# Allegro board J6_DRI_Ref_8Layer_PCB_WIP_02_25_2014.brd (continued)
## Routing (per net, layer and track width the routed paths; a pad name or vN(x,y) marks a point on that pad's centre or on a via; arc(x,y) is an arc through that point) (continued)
H_DDR1_A13: length 131.1
  TOP w0.102: v1(57.54,55.59) U52.AF18
  TOP w0.127: U65.T3 TP1MA23.1 ; TP1MC23.1 55.45,20.25 U67.N3 ; RN6.3 v1(62.39,19.64) ; U66.T3 TP1MB23.1
  L3-SIGNAL w0.114: TP1MB23.1 43.53,20.09 42.32,20.09 41.76,19.54 41.05,19.54 40.54,20.04 40.08,20.04 39.62,20.5 38.84,20.5 38.25,19.92 37.69,19.92 36.83,19.05 34.77,19.05 34.24,19.59 33.93,19.59 33.45,19.1 33.12,19.1 32.84,19.38 32.84,19.61 32.61,19.84 TP1MA23.1 ; v1(62.39,19.64) 61.99,19.25 56.78,19.25 56.17,19.85 TP1MC23.1
  BOTTOM w0.127: TP1MB23.1 45.44,19.84 45.8,20.2 46.94,20.2 47.93,19.2 48.95,19.2 49.38,19.64 49.78,19.64 49.89,19.54 49.89,19.15 49.99,19.05 50.19,19.05 50.29,19.15 50.29,19.54 50.42,19.66 51.13,19.66 51.28,19.51 51.28,19.2 51.38,19.1 51.74,19.1 51.92,19.28 52.33,19.28 52.51,19.1 52.92,19.1 53.1,19.28 53.51,19.28 53.69,19.1 54.1,19.1 54.28,19.28 54.58,19.28 54.77,19.1 55.09,19.1 TP1MC23.1 ; TP1MA23.1 30.85,20.07 29.34,20.07 28.96,19.69 28.47,19.69 28.3,19.87 27.99,19.87 27.81,19.69 25.68,19.69 25.35,20.02 25.35,20.47 25.21,20.61 24.75,20.61 24.24,21.13 24.24,21.4 24.48,21.63 24.48,21.8 24.36,21.92 24.19,21.92 23.95,21.68 23.56,21.68 23.06,22.18 23.06,22.43 23.19,22.56 23.6,22.56 23.88,22.84 23.88,23.6 23.42,24.06 23.42,24.2 23.61,24.4 23.61,24.55 23.47,24.69 23.33,24.69 23.09,24.45 22.92,24.45 22.8,24.57 22.8,24.74 23.04,24.98 23.04,25.12 22.9,25.27 22.75,25.27 22.53,25.04 22.36,25.04 21.56,25.83 20.68,25.83 20.42,26.09 20.42,26.22 20.52,26.32 20.8,26.32 20.9,26.42 20.9,26.6 20.8,26.7 20.6,26.7 20.5,26.8 20.5,26.98 20.6,27.08 21.31,27.08 21.41,27.18 21.41,27.38 21.31,27.49 20.62,27.49 20.52,27.59 20.52,27.79 20.62,27.89 21.31,27.89 21.41,27.99 21.41,28.2 21.31,28.3 20.62,28.3 20.52,28.4 20.52,28.6 20.62,28.7 21.31,28.7 21.41,28.81 21.41,29.01 21.31,29.11 20.62,29.11 20.52,29.21 20.52,29.42 20.62,29.52 21.31,29.52 21.41,29.62 21.41,29.82 21.31,29.92 20.62,29.92 20.52,30.03 20.52,30.23 20.62,30.33 21.31,30.33 21.41,30.43 21.41,30.63 21.31,30.74 20.62,30.74 20.52,30.84 20.52,31.45 20.35,31.63 20.14,31.63 20.02,31.75 20.02,32.41 20.12,32.51 20.79,32.51 20.9,32.63 20.9,32.8 20.79,32.92 20.12,32.92 20.02,33.02 20.02,33.23 20.12,33.33 20.96,33.33 21.08,33.45 21.08,33.61 20.96,33.73 20.12,33.73 20.02,33.84 20.02,34.04 20.12,34.14 20.79,34.14 20.9,34.26 20.9,34.43 20.79,34.55 20.32,34.55 20.19,34.67 20.19,34.85 20.32,34.98 21.29,34.98 23.06,36.76 23.06,36.96 35.46,49.35 40.46,49.35 40.72,49.1 40.94,49.1 41.05,49.2 41.05,49.36 41.17,49.48 41.33,49.48 41.45,49.36 41.45,49.2 41.55,49.1 41.76,49.1 41.86,49.2 41.86,49.36 41.98,49.48 42.15,49.48 42.27,49.36 42.27,49.2 42.37,49.1 42.57,49.1 42.67,49.2 42.67,49.36 42.79,49.48 42.96,49.48 43.08,49.36 43.08,49.2 43.18,49.1 43.38,49.1 43.48,49.2 43.48,49.36 43.6,49.48 43.77,49.48 43.89,49.36 43.89,49.2 43.99,49.1 44.86,49.1 49.68,53.93 50.29,53.93 51.65,55.29 57.23,55.29 v1(57.54,55.59)
H_DDR1_A14: length 116.3
  TOP w0.102: v1(59.13,56.41) U52.AE17
  TOP w0.127: TP1MC24.1 58.65,20.25 U67.N7 ; U65.T7 TP1MA24.1 ; U66.T7 TP1MB24.1
  L3-SIGNAL w0.114: v2(19.38,25.22) 19.38,32.59 21,34.21 21,34.35 20.89,34.46 20.89,34.6 21.03,34.75 21.17,34.75 21.28,34.64 21.43,34.64 21.57,34.78 21.57,35.15 21.74,35.32 22.18,35.32 29.98,43.13 31.83,43.13 34.75,46.05 40.84,46.05 47.32,52.53 51.89,52.53 52.35,52.99 54.94,52.99 56.57,54.61 58.39,54.61 58.9,55.12 59.36,55.12 59.54,55.3 59.54,56 v1(59.13,56.41)
  BOTTOM w0.127: v2(19.38,25.22) 22.89,21.72 22.89,21.03 25.02,18.9 29.34,18.9 29.57,19.13 30.15,19.13 30.28,19 30.78,19 31.17,19.38 33.05,19.38 TP1MA24.1 34.25,19.76 34.72,19.29 34.72,19.05 34.9,18.87 35.84,18.87 36.02,18.7 36.4,18.7 36.58,18.87 37.34,18.87 37.59,18.62 38.71,18.62 39.07,18.98 39.83,18.98 40.01,18.8 42.06,18.8 42.39,19.13 42.77,19.13 42.93,18.98 43.38,18.98 43.73,19.32 44.89,19.32 45.34,18.87 45.69,18.87 46.13,19.31 TP1MB24.1 46.74,19.76 47.88,18.62 49,18.62 49.28,18.9 49.56,18.9 49.83,18.62 51.32,18.62 51.33,18.61 56.1,18.61 56.29,18.8 56.64,18.8 56.88,18.56 57.06,18.56 57.21,18.71 57.21,18.89 56.88,19.22 56.88,19.36 57.02,19.51 57.16,19.51 57.46,19.21 57.61,19.21 TP1MC24.1 58.82,20.42 59.28,20.42 60.5,19.2 62.55,19.2 62.98,19.64 RN17.2
H_DDR1_A15: length 103.1
  TOP w0.102: U52.AD18 v1(59.98,55.63)
  TOP w0.127: TP1MC9.1 U67.J7 ; U65.M7 33.66,23.69 33.53,23.82 33.53,23.97 33.66,24.09 TP1MA11.1 ; TP1MB11.1 46.36,24.09 46.23,23.97 46.23,23.82 46.36,23.69 U66.M7
  L3-SIGNAL w0.114: TP1MA11.1 35.32,24.09 35.74,24.51 36.91,24.51 36.93,24.49 45.05,24.49 45.71,23.82 46.09,23.82 46.37,24.09 TP1MB11.1
  BOTTOM w0.102: 60.33,52.89 60.33,54.95 59.98,55.31 ; 59.46,52.02 58.98,52.02 58.94,52.05 58.16,52.05
  BOTTOM w0.127: 58.16,52.05 57.81,52.4 57.2,52.4 56.01,51.21 54.09,51.21 53.71,50.83 50.37,50.83 40.49,40.95 34.21,40.95 33.6,40.34 32.59,40.34 28.46,36.21 27.97,36.21 27,35.24 27,30.3 26.37,29.67 26.37,28.86 25.81,28.3 25.81,26.34 26.16,25.99 27.38,25.99 27.48,26.09 29.65,26.09 29.89,25.85 29.89,25.53 30.12,25.3 30.92,25.3 31.06,25.16 32.02,25.16 32.33,25.48 32.59,25.48 32.72,25.35 32.72,25.1 32.33,24.72 32.33,24.41 32.94,23.8 33.53,23.8 33.82,24.09 TP1MA11.1 ; 59.98,55.31 v1(59.98,55.63) ; 59.46,52.02 60.33,52.89 ; RN13.1 63.6,25.93 62.36,24.69 61.59,24.69 61.21,25.07 60.4,25.07 60.38,25.05 58.88,25.05 58.57,24.74 58.34,24.74 TP1MC9.1 58.01,24.41 57.35,24.41 57.23,24.54 56.64,24.54 56.31,24.21 55.88,24.21 55.52,24.56 55.52,24.87 55.89,25.24 55.89,25.39 55.79,25.49 55.64,25.49 55.11,24.95 55.11,24.77 54.92,24.59 54.76,24.59 54.64,24.72 54.64,24.92 54.51,25.05 54.08,25.05 53.52,24.49 51.16,24.49 51,24.34 50.22,24.34 50.06,24.49 48.41,24.49 48.18,24.26 48.18,24.01 47.98,23.8 47.28,23.8 TP1MB11.1
H_DDR1_BA0: length 128.3
  TOP w0.102: v1(57.53,56.44) U52.AF17
  TOP w0.127: U65.M2 29.88,23.43 29.78,23.33 29.63,23.33 29.48,23.48 TP1MA9.1 ; TP1MC10.1 U67.J2 ; RN2.4 v1(63.02,25.93) ; U66.M2 42.58,23.43 42.48,23.33 42.33,23.33 42.18,23.48 TP1MB9.1
  L3-SIGNAL w0.114: v1(63.02,25.93) 62.4,25.93 60.74,24.27 59.69,24.27 59.41,23.99 55.51,23.99 55.26,24.24 54.63,24.24 TP1MC10.1 53.86,24.24 52.08,24.24 51.36,23.52 50.45,23.52 49.83,22.91 46.77,22.91 46.58,23.09 45.39,23.09 44.96,23.52 42.75,23.52 TP1MB9.1 41.76,23.68 38.38,23.68 37.97,24.08 36.53,24.08 36.41,23.97 36.41,23.71 36.27,23.57 35.79,23.57 35.56,23.8 34.86,23.8 34.75,23.69 33.97,23.69 33.86,23.8 33.53,23.8 33.43,23.69 30.55,23.69 30.38,23.52 30.05,23.52 TP1MA9.1 29.09,23.7 26.57,23.7 26.21,24.06 23.52,24.06 22.94,24.64 22.94,26.88 22.81,27 22.5,27 22.38,26.88 v2(22.38,23.7)
  BOTTOM w0.127: v1(57.53,56.44) 57.12,56.44 56.48,55.8 51.2,55.8 50.04,54.64 49.45,54.64 45.06,50.24 35.26,50.24 32.13,47.12 31.99,47.12 31.76,47.35 31.6,47.35 31.48,47.23 31.48,47.06 31.7,46.83 31.7,46.69 31.56,46.55 31.41,46.55 31.19,46.77 31.02,46.77 30.9,46.65 30.9,46.48 31.13,46.26 31.13,46.12 30.98,45.97 30.84,45.97 30.61,46.2 30.45,46.2 30.33,46.08 30.33,45.91 30.55,45.68 30.55,45.54 30.41,45.4 30.26,45.4 30.04,45.62 29.87,45.62 29.75,45.5 29.75,45.33 29.98,45.11 29.98,44.97 29.83,44.82 29.69,44.82 29.46,45.05 29.3,45.05 29.18,44.93 29.18,44.76 29.4,44.53 29.4,44.39 29.26,44.25 29.11,44.25 28.89,44.47 28.72,44.47 28.6,44.35 28.6,44.18 28.83,43.96 28.83,43.82 28.68,43.67 28.54,43.67 28.24,43.97 28.09,43.97 27.95,43.83 27.95,43.68 28.25,43.38 28.25,43.24 28.11,43.1 27.96,43.1 27.66,43.4 27.52,43.4 27.38,43.25 27.38,43.11 27.68,42.81 27.68,42.67 27.53,42.52 27.39,42.52 27.09,42.82 26.94,42.82 26.8,42.68 26.8,42.53 27.1,42.23 27.1,42.09 26.96,41.95 26.81,41.95 26.51,42.25 26.37,42.25 26.23,42.1 26.23,41.96 26.53,41.66 26.53,41.52 26.38,41.37 26.24,41.37 26.08,41.53 25.9,41.53 22.16,37.78 22.16,37.6 22.31,37.44 22.31,37.3 22.17,37.16 22.02,37.16 21.72,37.46 21.58,37.46 21.44,37.31 21.44,37.17 21.74,36.87 21.74,36.73 21.59,36.58 21.45,36.58 21.15,36.88 21,36.88 20.86,36.74 20.86,36.59 21.16,36.29 21.16,36.15 21.02,36.01 20.87,36.01 20.57,36.31 20.43,36.31 19.25,35.13 19.25,26.11 20.41,24.95 20.56,24.95 20.67,25.07 20.84,25.07 20.96,24.95 20.96,24.78 20.85,24.66 20.85,24.52 20.99,24.38 21.13,24.38 21.24,24.48 21.41,24.48 21.53,24.36 21.53,24.2 21.42,24.09 21.42,23.95 21.67,23.7 v2(22.38,23.7)
H_DDR1_BA1: length 124.2
  TOP w0.102: v1(58.32,55.6) U52.AE18
  TOP w0.127: TP1MC12.1 U67.K8 ; TP1MB12.1 47.78,22.56 47.66,22.43 47.51,22.43 47.38,22.56 U66.N8 ; TP1MA12.1 35.08,22.56 34.96,22.43 34.81,22.43 34.68,22.56 U65.N8
  L3-SIGNAL w0.114: v2(23.01,23.07) 23.01,23.5 23.14,23.62 25.1,23.62 25.2,23.52 25.2,22.68 25.32,22.56 25.48,22.56 25.55,22.63 25.55,23.45 25.73,23.62 26.01,23.62 26.36,23.28 26.96,23.28 27.19,23.04 27.6,23.04 27.85,23.29 28.68,23.29 29.01,22.96 29.77,22.96 29.97,23.17 30.59,23.17 30.79,23.37 31.2,23.37 31.3,23.27 31.71,23.27 31.81,23.37 32.22,23.37 32.32,23.27 32.72,23.27 32.83,23.37 33.23,23.37 33.33,23.27 33.74,23.27 33.84,23.37 34.25,23.37 34.35,23.27 35.06,23.27 TP1MA12.1
  BOTTOM w0.127: TP1MA12.1 35.59,23.29 35.99,23.7 36.33,23.7 36.56,23.93 37.07,23.93 37.3,23.7 37.8,23.7 38.03,23.93 38.54,23.93 38.77,23.7 39.19,23.7 39.99,24.5 41.01,24.5 41.48,24.97 42.04,24.97 42.51,24.5 43.37,24.5 44.17,23.7 46.33,23.7 46.74,23.29 TP1MB12.1 48.09,23.29 48.26,23.46 48.51,23.46 48.7,23.27 48.87,23.27 49,23.4 49,23.95 49.15,24.11 49.81,24.11 50.01,23.9 51.18,23.9 51.51,24.23 52.32,24.23 52.45,24.11 52.45,23.65 52.58,23.52 52.8,23.52 52.92,23.65 52.92,24.13 53.04,24.25 55.31,24.25 55.73,23.83 56.46,23.83 56.77,24.13 57.1,24.13 57.23,24.01 58.22,24.01 58.42,24.21 59.03,24.21 59.39,23.85 TP1MC12.1 60.26,23.45 61.06,23.45 61.36,23.74 62.62,23.74 62.85,23.98 63.19,23.98 63.6,23.57 RN15.3 ; v1(58.32,55.6) 57.7,56.01 57.33,56.01 56.86,55.54 51.43,55.54 50.11,54.23 49.53,54.23 45.16,49.86 35.51,49.86 26.22,40.57 26.08,40.57 26,40.65 25.83,40.65 25.71,40.53 25.71,40.36 25.79,40.29 25.79,40.14 25.65,40 25.5,40 25.28,40.22 25.11,40.22 24.99,40.1 24.99,39.94 25.21,39.71 25.21,39.57 25.07,39.42 24.93,39.42 24.7,39.65 24.53,39.65 24.41,39.53 24.41,39.36 24.64,39.14 24.64,38.99 24.5,38.85 24.35,38.85 24.13,39.07 23.96,39.07 23.84,38.95 23.84,38.79 24.06,38.56 24.06,38.42 23.92,38.27 23.78,38.27 23.55,38.5 23.38,38.5 23.26,38.38 23.26,38.21 23.49,37.99 23.49,37.84 23.34,37.7 23.2,37.7 22.98,37.92 22.81,37.92 22.69,37.8 22.69,37.64 22.91,37.41 22.91,37.27 21.2,35.56 20.19,35.56 19.63,35 19.63,31.4 19.74,31.3 20.04,31.3 20.14,31.2 20.14,30.99 20.04,30.89 19.74,30.89 19.63,30.79 19.63,30.59 19.74,30.48 20.04,30.48 20.14,30.38 20.14,30.18 20.04,30.08 19.74,30.08 19.63,29.98 19.63,29.77 19.74,29.67 20.04,29.67 20.14,29.57 20.14,29.37 20.04,29.27 19.74,29.27 19.63,29.16 19.63,28.96 19.74,28.86 20.04,28.86 20.14,28.76 20.14,28.55 20.04,28.45 19.74,28.45 19.63,28.35 19.63,28.15 19.74,28.05 20.04,28.05 20.14,27.94 20.14,27.74 20.04,27.64 19.74,27.64 19.63,27.54 19.63,27.34 19.74,27.23 20.04,27.23 20.14,27.13 20.14,26.93 20.04,26.83 19.74,26.83 19.63,26.73 19.63,26.37 20.55,25.45 21.31,25.45 23.01,23.75 v2(23.01,23.07)
H_DDR1_BA2: length 130.4
  TOP w0.102: 61.13,56.05 v1(61.53,55.65)
  TOP w0.127: TP1MA15.1 31.73,23.05 31.6,23.17 31.2,23.17 U65.M3 ; TP1MC11.1 U67.J3 ; U66.M3 43.9,23.17 44.3,23.17 44.43,23.05 TP1MB15.1
  L3-SIGNAL w0.102: 56.96,53.71 58.6,53.71 58.66,53.65 59.36,53.65 59.56,53.85 59.56,54.19 59.76,54.38 60.1,54.38 60.33,54.62 60.33,55.37 60.36,55.4 60.36,55.86 60.58,56.09 61.09,56.09 v1(61.53,55.65)
  L3-SIGNAL w0.114: v2(53.16,51.89) 55.14,51.89 56.96,53.71 ; TP1MA15.1 32.04,22.42 32.52,21.94 33.69,21.94 33.84,22.08 34.77,22.08 35.29,21.56 36.85,21.56 36.98,21.69 41.22,21.69 41.61,22.08 43.64,22.08 43.99,22.42 TP1MB15.1
  BOTTOM w0.127: RN15.2 61.65,23.07 61.21,22.63 59.69,22.63 59.42,22.9 59.42,23.13 58.98,23.57 56.92,23.57 56.79,23.45 55.45,23.45 TP1MC11.1 54.65,23.46 53.28,23.46 52.96,23.14 52.2,23.14 52.07,23.27 52.07,23.68 51.94,23.8 51.66,23.8 51.38,23.52 49.92,23.52 49.8,23.4 49.8,23 49.63,22.84 48.8,22.84 48.7,22.94 48.23,22.94 48.17,22.88 46.56,22.88 46.09,23.35 44.39,23.35 44.27,23.23 44.27,23.06 44.39,22.94 45.09,22.94 45.21,22.81 45.21,22.55 45.09,22.42 TP1MB15.1 ; v2(53.16,51.89) 52.7,51.89 52.53,51.72 49.9,51.72 43.35,45.16 43.13,45.16 42.91,45.39 42.65,45.39 42.55,45.28 42.55,44.83 42.43,44.71 42.27,44.71 42.15,44.83 42.15,45.81 42.03,45.93 41.86,45.93 41.74,45.81 41.74,44.76 41.64,44.66 41.44,44.66 41.33,44.76 41.33,45.81 41.21,45.93 41.05,45.93 40.93,45.81 40.93,44.76 40.83,44.66 40.62,44.66 40.52,44.76 40.52,45.3 40.4,45.42 40.23,45.42 40.11,45.3 40.11,44.76 40.01,44.66 39.81,44.66 39.71,44.76 39.71,45.28 39.61,45.39 38.96,45.39 38.86,45.49 38.86,45.68 38.74,45.8 38.58,45.8 38.46,45.68 38.46,45.28 38.34,45.16 38.17,45.16 38.05,45.28 38.05,45.68 37.93,45.8 37.76,45.8 37.64,45.68 37.64,45.28 37.52,45.16 37.36,45.16 37.24,45.28 37.24,45.68 37.12,45.8 36.95,45.8 36.83,45.68 36.83,45.28 36.71,45.16 36.54,45.16 36.42,45.28 36.42,45.68 36.3,45.8 36.14,45.8 36.02,45.68 36.02,45.28 35.9,45.16 35.73,45.16 35.61,45.28 35.61,45.55 35.49,45.67 35.32,45.67 35.2,45.55 35.2,45.29 35.08,45.16 34.62,45.16 34.49,45.04 34.49,44.91 34.34,44.76 33.88,44.76 32.84,43.72 32.84,43.13 32.75,43.04 32.2,43.04 32.08,42.92 32.08,42.75 32.2,42.62 32.59,42.62 32.71,42.5 32.71,42.36 32.59,42.24 32.33,42.24 32.22,42.12 32.22,41.98 32.33,41.86 32.59,41.86 32.71,41.74 32.71,41.6 32.59,41.48 32.08,41.48 31.83,41.73 31.45,41.73 31.1,41.39 30.52,41.39 26.05,36.92 26.05,36.78 26.31,36.52 26.31,36.35 26.19,36.23 26.03,36.23 25.76,36.49 25.62,36.49 25.43,36.3 25.43,29.42 25.3,29.29 24.49,29.29 24.36,29.16 24.36,28.29 24.26,28.19 23.8,28.19 23.7,28.09 23.7,27.89 23.8,27.79 24.26,27.79 24.36,27.68 24.36,26.84 24.26,26.74 23.8,26.74 23.7,26.64 23.7,26.43 23.8,26.33 24.26,26.33 24.36,26.23 24.36,25.38 25.3,24.44 25.3,22.61 25.55,22.35 27.94,22.35 28.09,22.5 28.78,22.5 28.91,22.38 28.91,22.18 29.03,22.05 29.29,22.05 29.41,22.18 29.41,22.43 29.87,22.89 30.62,22.89 30.79,22.72 30.79,21.92 30.94,21.77 31.19,21.77 31.32,21.9 31.32,22.3 31.45,22.42 TP1MA15.1
H_DDR1_CASN: length 117.2
  TOP w0.102: U52.AC18 v1(60.77,55.66)
  TOP w0.127: RN2.2 v1(63.02,27) ; U66.K3 43.55,25.13 44.33,25.13 44.5,25.3 TP1MB3.1 ; U65.K3 30.85,25.13 31.63,25.13 31.8,25.3 TP1MA3.1 ; TP1MC5.1 U67.G3
  L3-SIGNAL w0.102: 57.32,51.26 58.16,51.26 58.54,51.26 58.73,51.44 58.73,51.82 58.93,52.02 59.74,52.02 ; 60.93,53.65 60.55,53.65 60.35,53.45 60.35,53.06 59.92,52.63
  L3-SIGNAL w0.114: TP1MA3.1 31.26,26.24 28.14,26.24 26.75,27.64 26.75,30.15 26.86,30.26 27.42,30.26 27.53,30.37 27.53,30.6 27.42,30.72 26.86,30.72 26.75,30.83 26.75,31.05 26.85,31.15 28.79,31.15 28.91,31.27 28.91,31.44 28.79,31.56 26.85,31.56 26.75,31.66 26.75,31.86 26.85,31.96 28.02,31.96 28.14,32.08 28.14,32.25 28.02,32.37 26.85,32.37 26.75,32.47 26.75,32.67 26.85,32.77 28.02,32.77 28.14,32.89 28.14,33.06 28.02,33.18 27.17,33.18 27,33.35 27,34.11 27.27,34.39 27.42,34.39 27.65,34.15 27.8,34.15 27.94,34.29 27.94,34.44 27.7,34.67 27.7,34.82 27.85,34.96 27.99,34.96 28.23,34.72 28.37,34.72 28.52,34.87 28.52,35.01 28.28,35.25 28.28,35.39 28.42,35.54 28.57,35.54 28.8,35.3 28.95,35.3 29.09,35.44 29.09,35.59 28.85,35.82 28.85,35.97 29,36.11 29.14,36.11 29.38,35.87 29.52,35.87 29.67,36.02 29.67,36.16 29.43,36.4 29.43,36.54 29.57,36.69 29.72,36.69 29.95,36.45 30.1,36.45 30.24,36.59 30.24,36.74 30,36.97 30,37.12 30.18,37.29 30.18,37.8 30.35,37.97 30.49,37.97 30.85,37.61 31,37.61 31.14,37.75 31.14,37.89 30.78,38.26 30.78,38.4 31.45,39.07 32.21,39.07 36.53,43.39 42.62,43.39 49.35,50.12 50.14,50.12 50.24,50.02 50.24,49.71 50.34,49.61 50.54,49.61 50.64,49.71 50.64,50.02 50.75,50.12 50.95,50.12 51.05,50.02 51.05,49.71 51.15,49.61 51.36,49.61 51.46,49.71 51.46,50.02 51.56,50.12 51.76,50.12 51.86,50.02 51.86,49.71 51.97,49.61 52.17,49.61 52.27,49.71 52.27,50.02 52.37,50.12 52.58,50.12 52.68,50.02 52.68,49.71 52.78,49.61 52.98,49.61 53.08,49.71 53.08,50.02 53.18,50.12 56.18,50.12 57.32,51.26 ; v1(63.02,27) 62.07,27 60.15,25.07 59.69,25.07 59.56,25.2 58.57,25.2 58.42,25.05 57.12,25.05 56.72,25.45 TP1MC5.1 54.65,25.85 53.89,25.85 53.67,25.63 50.6,25.63 49.86,24.89 49.12,24.89 48.92,25.1 48.54,25.1 47.95,24.51 47.61,24.51 47.14,24.97 45.75,24.97 45.29,25.43 45.03,25.43 44.83,25.22 44.63,25.22 44.5,25.35 TP1MB3.1 ; 59.92,52.63 59.92,52.2 59.74,52.02 ; v1(60.77,55.66) 61.12,55.31 61.12,53.84 60.93,53.65
  BOTTOM w0.127: TP1MB3.1 44.28,25.92 44.28,26.05 43.87,26.47 39.8,26.47 39.45,26.11 37.77,26.11 36.93,25.28 36.09,25.28 35.27,26.1 33.81,26.1 33.74,26.16 32.26,26.16 TP1MA3.1
H_DDR1_CKE: length 126.4
  TOP w0.127: TP1MC3.1 60.65,26.26 U67.G9 ; U66.K9 48.43,25.04 48.72,25.04 TP1MB2.1 ; U52.AG22 56.76,52.48 55.93,52.48 55.46,52.01 54.06,52.01 53.49,51.44 52.86,51.44 51.99,52.3 49.96,52.3 42.12,44.46 41.98,44.46 41.89,44.55 41.75,44.55 41.61,44.4 41.61,44.26 41.69,44.17 41.69,44.03 41.39,43.73 41.1,43.73 41,43.83 41,44.31 40.88,44.43 40.71,44.43 40.59,44.31 40.59,43.63 40.47,43.51 40.31,43.51 40.19,43.63 40.19,44.66 40.07,44.78 39.9,44.78 39.78,44.66 39.78,43.83 39.68,43.73 39.48,43.73 39.37,43.83 39.37,44.66 39.26,44.78 39.09,44.78 38.97,44.66 38.97,43.83 38.87,43.73 38.66,43.73 38.56,43.83 38.56,44.66 38.44,44.78 38.27,44.78 38.16,44.66 38.16,43.83 38.05,43.73 37.85,43.73 37.75,43.83 37.75,44.66 37.63,44.78 37.46,44.78 37.34,44.66 37.34,43.83 37.24,43.73 37.04,43.73 36.94,43.83 36.94,44.66 36.82,44.78 36.65,44.78 36.53,44.66 36.53,43.83 36.43,43.73 36.23,43.73 36.12,43.83 36.12,44.66 36,44.78 35.84,44.78 35.72,44.66 35.72,43.83 35.62,43.73 35.41,43.73 35.31,43.83 35.31,44.66 35.19,44.78 35.02,44.78 34.9,44.66 34.9,43.83 34.8,43.73 34.6,43.73 34.5,43.83 34.5,44.66 34.38,44.78 34.21,44.78 34.09,44.66 34.09,43.83 33.99,43.73 33.79,43.73 33.69,43.83 33.69,44.55 33.58,44.66 33.38,44.66 33.28,44.55 33.28,43.8 33.15,43.67 32.44,43.67 32.33,43.57 32.33,43.37 32.44,43.26 32.74,43.26 32.84,43.16 32.84,42.96 32.74,42.86 32.44,42.86 32.33,42.76 32.33,42.55 32.44,42.45 32.74,42.45 32.84,42.35 32.84,42.12 32.72,41.99 32.46,41.99 32.21,41.73 31.7,41.73 31.38,42.06 30.24,42.06 30.02,41.84 30.02,41.69 30.13,41.58 30.13,41.44 29.99,41.29 29.84,41.29 29.73,41.4 29.59,41.4 29.45,41.26 29.45,41.12 29.56,41.01 29.56,40.86 29.41,40.72 29.27,40.72 29.16,40.83 29.02,40.83 28.87,40.68 28.87,40.54 28.98,40.43 28.98,40.29 28.84,40.14 28.69,40.14 28.58,40.25 28.44,40.25 28.3,40.11 28.3,39.97 28.41,39.86 28.41,39.71 28.26,39.57 28.12,39.57 28.01,39.68 27.87,39.68 27.72,39.53 27.72,39.39 27.83,39.28 27.83,39.14 27.69,38.99 27.54,38.99 27.43,39.1 27.29,39.1 27.15,38.96 27.15,38.82 27.26,38.71 27.26,38.56 27.11,38.42 26.97,38.42 26.86,38.53 26.72,38.53 26.57,38.38 26.57,38.24 26.68,38.13 26.68,37.99 26.54,37.84 26.39,37.84 26.28,37.95 26.14,37.95 26,37.81 26,37.67 26.11,37.56 26.11,37.41 25.96,37.27 25.82,37.27 25.71,37.38 25.57,37.38 25.42,37.23 25.42,37.09 25.53,36.98 25.53,36.84 25.39,36.69 25.24,36.69 25.13,36.8 24.99,36.8 24.59,36.4 24.59,31.57 25.35,30.81 25.35,26.62 25.48,26.49 v2(26.31,26.49) ; TP1MA2.1 36.02,25.04 35.73,25.04 U65.K9
  L3-SIGNAL w0.102: TP1MC3.1 60.65,27.07 61.65,28.07 62.41,28.07 v1(62.99,28.65)
  BOTTOM w0.127: TP1MC3.1 59.59,27.07 59.46,27.19 59.46,27.35 59.33,27.47 57.86,27.47 57.73,27.35 57.73,27.16 57.61,27.03 57.32,27.03 57.19,27.16 57.19,27.49 57.06,27.61 55.65,27.61 55.52,27.49 55.52,26.8 55.37,26.65 52.37,26.65 52.02,27 51.77,27 51.64,26.88 51.64,26.72 51.51,26.6 51.36,26.6 51.23,26.72 51.23,26.88 51.1,27 50.55,27 50.37,26.82 49.81,26.82 49.43,26.44 TP1MB2.1 48.9,25.75 48.62,26.04 48.11,26.04 47.24,26.9 46.66,26.9 46.43,26.67 45.96,26.67 45.75,26.88 45.47,26.88 45.24,26.65 44.91,26.65 44.68,26.88 40.08,26.88 39.95,27 37.98,27 37.61,26.64 37.43,26.64 37.36,26.71 37.18,26.71 37,26.53 37,26.36 37.07,26.28 37.07,26.1 TP1MA2.1 36.42,26.06 35.71,26.06 34.87,26.9 33.07,26.9 32.65,27.32 32.25,27.32 32.16,27.23 31.45,27.23 31,27.69 29.32,27.69 29.09,27.46 29.09,26.88 28.7,26.49 v2(26.31,26.49) ; R689.1 v1(62.99,28.65)
H_DDR1_CLK0: length 110.8
  TOP w0.089: U65.J7 TP1MA1.1 ; U66.J7 TP1MB1.1 ; 56.4,50.84 56.81,51.25 U52.AG24 ; U67.F7 TP1MC2.1 ; 53.8,50.28 53.73,50.35 50.59,50.35 47.07,46.82 47.07,45.46 46.91,45.31 45.67,45.31 45.36,45 45.06,45 44.93,44.87 44.93,43.16 44.51,42.74 43.85,42.74 43.72,42.61 43.72,41.76 43.56,41.61 42.51,41.61 42.51,40.6 42.22,40.32 41.69,40.32 40.97,41.04 40.79,41.04 40.57,40.83 40.57,40.65 41.3,39.93 41.3,39.53 40.88,39.11 40.48,39.11 39.77,39.82 37.91,39.82 37.63,39.54 37.63,37.43 37.35,37.15 36.65,37.15 36.53,37.28 36.53,40.21 36.4,40.34 36.05,40.34 35.92,40.21 35.92,37.43 35.64,37.15 35.05,37.15 34.76,37.43 34.76,39.32 34.64,39.45 32.53,39.45 32.4,39.32 32.4,37.99 30.52,36.12 29.26,36.12 29.18,36.04 29.18,34.14 28.66,33.62 27.83,33.62 27.49,33.96 27.08,33.96 26.86,33.74 26.86,32.71 26.94,32.63 27.87,32.63 28.16,32.35 28.16,31.76 27.87,31.47 26.94,31.47 26.86,31.39 26.86,31 26.94,30.92 28,30.92 28.28,30.64 28.28,30.04 28,29.76 26.94,29.76 26.68,29.5 26.68,28.55 26.8,28.44 27.04,28.44 v1(27.2,28.6)
  TOP w0.102: 53.8,50.28 54.44,50.28 54.78,50.61 55.44,50.61 55.67,50.84 56.4,50.84
  L3-SIGNAL w0.102: v2(62.92,30.69) 62.6,30.37 61.94,30.37 61.44,29.87 61.44,28.83 59.28,26.67 58.64,26.67 TP1MC2.1 57.98,26.79 56.91,26.79 56.81,26.69 54.89,26.69 54.57,27 49.73,27 48.84,26.11 48.34,26.11 48.11,26.34 47.14,26.34 TP1MB1.1 46.71,26.22 46.58,26.22 46.05,26.75 40.61,26.75 40.06,27.31 37.31,27.31 36.09,26.09 35.64,26.09 35.38,26.34 34.44,26.34 TP1MA1.1 34.01,26.22 33.9,26.22 33.66,26.47 31.95,26.47 31.6,26.82 28.42,26.82 28.12,27.13 28.12,27.99 27.76,28.35 27.46,28.35 v1(27.2,28.6)
  BOTTOM w0.089: v2(62.92,30.69) 63.65,30.69 R684.1
H_DDR1_CLK0N: length 111.1
  TOP w0.089: v1(27.2,27.84) 27.2,28.15 27.18,28.17 26.69,28.17 26.42,28.44 26.42,29.61 26.83,30.03 27.89,30.03 28.02,30.16 28.02,30.53 27.89,30.65 26.83,30.65 26.59,30.89 26.59,31.5 26.83,31.74 27.76,31.74 27.89,31.87 27.89,32.24 27.76,32.36 26.83,32.36 26.59,32.6 26.59,33.85 26.96,34.23 27.6,34.23 27.94,33.89 28.55,33.89 28.92,34.25 28.92,36.15 29.15,36.38 30.41,36.38 32.13,38.1 32.13,39.43 32.41,39.72 34.75,39.72 35.03,39.43 35.03,37.54 35.16,37.42 35.53,37.42 35.66,37.54 35.66,40.32 35.94,40.6 36.51,40.6 36.79,40.32 36.79,37.42 37.24,37.42 37.37,37.54 37.37,39.65 37.8,40.08 39.88,40.08 40.59,39.37 40.77,39.37 41.03,39.64 41.03,39.82 40.31,40.54 40.31,40.94 40.67,41.31 41.08,41.31 41.8,40.58 42.11,40.58 42.24,40.71 42.24,41.75 42.37,41.87 43.45,41.87 43.45,42.72 43.74,43.01 44.4,43.01 44.66,43.27 44.66,44.98 44.95,45.27 45.25,45.27 45.56,45.57 46.8,45.57 46.8,46.93 50.48,50.61 53.73,50.61 53.79,50.56 53.8,50.56 ; U66.K7 TP1MB4.1 ; U52.AH24 56.2,51.12 ; U67.G7 TP1MC4.1 ; U65.K7 TP1MA4.1
  TOP w0.102: 56.2,51.12 55.55,51.12 55.32,50.89 54.66,50.89 54.33,50.56 53.8,50.56
  L3-SIGNAL w0.102: v2(62.92,29.8) 62.6,30.11 62.04,30.11 61.7,29.77 61.7,28.73 59.39,26.42 58.4,26.42 TP1MC4.1 57.98,26.54 57.02,26.54 56.91,26.43 54.78,26.43 54.47,26.75 49.84,26.75 48.95,25.86 48.23,25.86 48,26.09 47.38,26.09 TP1MB4.1 46.71,25.97 46.47,25.97 45.94,26.49 40.51,26.49 39.95,27.05 37.42,27.05 36.2,25.83 35.53,25.83 35.28,26.09 34.68,26.09 TP1MA4.1 34.01,25.97 33.8,25.97 33.55,26.22 31.85,26.22 31.49,26.57 28.32,26.57 27.86,27.02 27.86,27.89 27.66,28.09 27.46,28.09 v1(27.2,27.84)
  BOTTOM w0.089: R687.1 63.65,29.8 v2(62.92,29.8)
H_DDR1_CSN0: length 129
  TOP w0.102: U65.L2 TP1MA10.1
  TOP w0.127: U66.L2 TP1MB10.1 ; TP1MC8.1 U67.H2 ; v1(27.08,25.22) 27.08,23.95 26.95,23.83 26.62,23.83 26.49,23.95 26.49,25.61 26.87,25.99 26.87,26.7 26.44,27.13 25.91,27.13 25.7,27.33 25.7,30.98 24.97,31.72 24.97,31.92 25.07,32.03 25.7,32.03 25.78,32.1 25.78,32.36 25.7,32.43 25.07,32.43 24.97,32.53 24.97,32.74 25.07,32.84 25.7,32.84 25.78,32.91 25.78,33.17 25.7,33.24 25.07,33.24 24.97,33.35 24.97,33.55 25.07,33.65 25.7,33.65 25.78,33.73 25.78,33.98 25.7,34.06 25.07,34.06 24.97,34.16 24.97,34.36 25.07,34.46 25.7,34.46 25.78,34.54 25.78,34.65 25.81,34.68 25.81,34.77 25.7,34.87 25.07,34.87 24.97,34.97 24.97,35.17 25.07,35.28 26.12,35.28 26.24,35.4 26.24,35.56 26.12,35.68 25.07,35.68 24.97,35.78 24.97,35.99 25.07,36.09 25.7,36.09 25.81,36.19 25.81,36.6 30.81,41.61 31.19,41.61 31.7,41.1 32.67,41.1 33.29,41.71 33.29,43.01 33.4,43.13 33.57,43.13 33.69,43.01 33.69,41.71 33.79,41.61 34,41.61 34.1,41.71 34.1,43.01 34.22,43.13 34.39,43.13 34.5,43.01 34.5,41.71 34.61,41.61 34.81,41.61 34.91,41.71 34.91,43.01 35.03,43.13 35.2,43.13 35.32,43.01 35.32,41.71 35.42,41.61 35.62,41.61 35.72,41.71 35.72,43.01 35.84,43.13 36.01,43.13 36.13,43.01 36.13,41.71 36.23,41.61 36.44,41.61 36.54,41.71 36.54,43.01 36.66,43.13 36.82,43.13 36.94,43.01 36.94,41.71 37.04,41.61 37.25,41.61 37.35,41.71 37.35,43.01 37.47,43.13 37.64,43.13 37.76,43.01 37.76,41.71 37.86,41.61 38.06,41.61 38.16,41.71 38.16,43.14 38.28,43.26 38.45,43.26 38.57,43.14 38.57,41.71 38.67,41.61 38.87,41.61 38.98,41.71 38.98,42.89 39.09,43 39.26,43 39.38,42.89 39.38,41.71 39.48,41.61 39.78,41.61 40.07,41.91 40.07,42.05 39.86,42.26 39.86,42.4 40.01,42.55 40.15,42.55 40.36,42.34 40.5,42.34 40.65,42.48 40.65,42.62 40.44,42.84 40.44,42.98 40.58,43.12 40.72,43.12 40.94,42.91 41.08,42.91 49.81,51.64 52.12,51.64 52.65,51.11 53.63,51.11 54.27,51.74 55.65,51.74 55.96,52.05 U52.AH23 ; RN2.3 v1(62.39,26.5)
  L3-SIGNAL w0.114: TP1MB10.1 44.92,24.09 45.41,23.61 47.3,23.61 47.38,23.68 48.8,23.68 48.97,23.85 50.8,23.85 51.6,24.65 TP1MC8.1 54.31,24.59 55.5,24.59 55.88,24.21 59.17,24.21 59.63,24.67 60.55,24.67 v1(62.39,26.5)
  BOTTOM w0.127: v1(27.08,25.22) 28.37,25.22 28.76,24.84 29.46,24.84 30.03,24.27 30.11,24.27 TP1MA10.1 30.7,24.09 30.81,24.21 31.57,24.21 32.66,23.12 33.53,23.12 33.76,22.89 34.09,22.89 34.24,23.04 34.59,23.04 34.75,22.89 36.35,22.89 36.63,22.61 36.98,22.61 37.31,22.28 37.82,22.28 38.38,22.84 38.91,22.84 39.93,23.85 40.77,23.85 40.92,23.7 41.5,23.7 41.63,23.57 42.06,23.57 42.19,23.7 42.59,23.7 TP1MB10.1
H_DDR1_D0: length 49.6
  TOP w0.102: v1(58.33,50.04) U52.AF25
  TOP w0.127: v1(32.66,28.15) U65.H7
  BOTTOM w0.127: v1(32.66,28.15) 32.29,28.52 32.29,28.67 32.35,28.73 32.35,28.9 32.23,29.02 32.06,29.02 32,28.96 31.85,28.96 31.71,29.1 31.71,29.24 31.77,29.3 31.77,29.47 31.65,29.59 31.48,29.59 31.42,29.53 31.28,29.53 31.01,29.8 31.01,30.81 32.33,32.13 32.33,37.47 33.27,38.41 34.24,38.41 34.57,38.08 34.57,36.88 34.92,36.53 39.52,36.53 49.9,46.9 50.97,46.9 51.26,47.2 51.26,47.58 51.13,47.7 51.13,48.14 51.33,48.34 51.33,49.04 51.6,49.3 54.61,49.3 54.95,49.65 56.55,49.65 56.72,49.48 56.72,49.23 56.85,49.1 57.35,49.1 57.48,49.23 57.48,50.24 57.61,50.37 58,50.37 v1(58.33,50.04)
H_DDR1_D1: length 44.9
  TOP w0.127: v2(51.64,47.83) 52.07,47.4 53.59,47.4 54.05,47.86 54.81,47.86 55.45,48.49 56.54,48.49 56.74,48.69 56.74,49.02 56.97,49.25 57.53,49.25 U52.AF26 ; U65.F8 v1(35.08,28.09)
  L3-SIGNAL w0.114: v2(51.64,47.83) 51.38,47.58 48.82,47.58 43.1,41.86 37.24,41.86 33.55,38.18 33.55,36.47 33.66,36.37 33.92,36.37 34.04,36.25 34.04,36.09 33.92,35.97 33.66,35.97 33.55,35.86 33.55,35.66 33.66,35.56 33.88,35.56 33.99,35.46 33.99,35.26 33.88,35.15 33.66,35.15 33.55,35.05 33.55,31.68 33.71,31.52 34.37,31.52 34.49,31.4 34.49,31.19 34.37,31.07 33.23,31.07 33.07,30.91 33.07,30.32 33.68,29.71 33.68,29.5 34.28,28.9 34.95,28.9 35.08,28.77 v1(35.08,28.09)
H_DDR1_D2: length 44.5
  TOP w0.127: v1(32.97,29.54) U65.F7 ; U52.AG26 56.86,49.65 56.49,49.28 54.66,49.28 54.58,49.2 53.89,49.2 53.84,49.25 52.32,49.25 v2(51.92,48.85)
  L3-SIGNAL w0.114: v1(32.97,29.54) 32.56,29.95 32.56,31.66 32.69,31.79 32.99,31.79 33.1,31.89 33.1,32.09 32.99,32.19 32.66,32.19 32.54,32.31 32.54,32.48 32.66,32.6 32.99,32.6 33.1,32.7 33.1,32.91 32.99,33.01 32.68,33.01 32.56,33.13 32.56,33.29 32.68,33.41 32.99,33.41 33.1,33.52 33.1,33.72 32.99,33.82 32.68,33.82 32.56,33.94 32.56,34.11 32.68,34.23 32.99,34.23 33.1,34.33 33.1,34.53 32.99,34.63 32.68,34.63 32.56,34.75 32.56,34.92 32.68,35.04 32.99,35.04 33.1,35.14 33.1,35.34 32.99,35.45 32.68,35.45 32.56,35.56 32.56,35.73 32.68,35.84 32.97,35.84 33.1,35.97 33.1,36.15 32.97,36.27 32.79,36.27 32.56,36.5 32.56,37.77 32.79,38 32.94,38 33.1,38.15 33.1,38.36 37.11,42.37 42.98,42.37 48.63,48.02 51.09,48.02 51.38,48.31 51.77,48.31 51.92,48.47 v2(51.92,48.85)
H_DDR1_D3: length 44.3
  TOP w0.127: v2(50.83,48.47) 51.87,49.51 55.42,49.51 55.57,49.65 U52.AH26 ; U65.H8 v1(35.08,27.29)
  L3-SIGNAL w0.114: v1(35.08,27.29) 34.74,27.64 34.03,27.64 33.87,27.8 33.87,28.64 33.6,28.91 33.05,28.91 32.82,28.68 32.33,28.68 32.16,28.86 32.16,38.05 36.98,42.88 42.82,42.88 48.41,48.47 48.7,48.47 48.81,48.58 48.81,48.81 48.92,48.92 49.15,48.92 49.27,48.81 49.27,48.58 49.38,48.47 49.61,48.47 49.72,48.58 49.72,48.81 49.84,48.92 50.07,48.92 50.18,48.81 50.18,48.58 50.3,48.47 v2(50.83,48.47)
H_DDR1_D4: length 49
  TOP w0.102: v1(57.53,50.8) U52.AF24
  TOP w0.127: v1(30.28,29.7) U65.E3
  BOTTOM w0.127: v1(57.53,50.8) 56.72,49.99 54.74,49.99 54.36,49.61 51.28,49.61 50.24,48.57 50.24,47.83 39.45,37.04 35.13,37.04 35,37.16 35,37.74 35.1,37.84 35.67,37.84 35.79,37.96 35.79,38.13 35.67,38.25 35.1,38.25 35,38.35 35,38.69 34.87,38.81 33.17,38.81 31.72,37.37 31.72,37.04 31.95,36.81 31.95,36.58 31.85,36.48 31.55,36.48 31.45,36.38 31.45,36.17 31.55,36.07 31.85,36.07 31.95,35.97 31.95,35.77 31.85,35.66 31.55,35.66 31.45,35.56 31.45,35.36 31.55,35.26 31.85,35.26 31.95,35.16 31.95,34.95 31.85,34.85 31.55,34.85 31.45,34.75 31.45,34.55 31.55,34.45 31.85,34.45 31.95,34.34 31.95,34.14 31.85,34.04 31.55,34.04 31.45,33.94 31.45,33.73 31.55,33.63 31.85,33.63 31.95,33.53 31.95,33.33 31.85,33.23 31.55,33.23 31.45,33.12 31.45,32.92 31.55,32.82 31.85,32.82 31.95,32.72 31.95,32.46 30.7,31.21 30.7,30.11 v1(30.28,29.7)
H_DDR1_D5: length 48.9
  TOP w0.102: v1(58.32,50.88) U52.AE24
  TOP w0.127: U65.H3 v1(31.78,27.64)
  BOTTOM w0.102: 29.87,29.39 29.87,29.97
  BOTTOM w0.127: 29.87,29.97 29.87,31.07 31.01,32.21 31.01,37.16 33.05,39.19 35.64,39.19 36.27,38.56 36.27,37.54 36.4,37.42 39.19,37.42 49.86,48.08 49.86,48.67 51.1,49.91 54.17,49.91 54.56,50.31 56.27,50.31 57.2,51.23 57.96,51.23 v1(58.32,50.88) ; 29.87,29.39 30.15,29.11 31.01,29.11 31.78,28.35 v1(31.78,27.64)
H_DDR1_D6: length 49.1
  TOP w0.102: v1(57.57,51.64) U52.AF23
  TOP w0.127: v1(29.48,28.9) U65.F2
  BOTTOM w0.102: 29.1,29.28 29.1,30.03 ; 29,31.85 29,33.19
  BOTTOM w0.127: 29,33.19 29.29,33.48 30.43,33.48 30.56,33.61 30.56,37.21 32.92,39.58 36.65,39.58 36.78,39.45 36.78,37.92 36.91,37.8 38.94,37.8 49.48,48.34 49.48,48.75 50.95,50.22 54.01,50.22 54.42,50.62 56.18,50.62 57.2,51.64 v1(57.57,51.64) ; 29,31.85 28.73,31.58 28.41,31.58 28.3,31.46 28.3,31.29 28.41,31.17 29,31.17 29.1,31.07 29.1,30.86 29,30.76 28.37,30.76 28.27,30.66 28.27,30.46 28.37,30.36 29,30.36 29.1,30.25 29.1,30.03 ; v1(29.48,28.9) 29.1,29.28
H_DDR1_D7: length 50.9
  TOP w0.102: U52.AE23 v1(58.35,51.67)
  TOP w0.127: v1(30.28,28.09) U65.G2
  BOTTOM w0.102: 57.67,52.07 58.07,51.67
  BOTTOM w0.127: v1(30.28,28.09) 28.4,28.09 27.58,27.28 26.9,27.28 26.75,27.43 26.75,29.54 27.3,30.1 27.3,34.27 30.11,37.07 30.11,37.23 32.84,39.96 40.46,39.96 49.1,48.59 49.1,48.85 50.77,50.52 53.87,50.52 54.27,50.92 56.1,50.92 57.25,52.07 57.67,52.07 ; 58.07,51.67 v1(58.35,51.67)
H_DDR1_D8: length 49.1
  TOP w0.102: U52.AC23 v1(60.72,52.45)
  TOP w0.127: U65.A2 29.88,33.14 29.78,33.25 29.51,33.25 29.41,33.35 29.41,33.55 29.51,33.65 29.78,33.65 29.88,33.75 29.88,34.33 31.61,36.05 31.61,36.2 31.5,36.31 31.5,36.45 31.64,36.59 31.78,36.59 31.89,36.48 32.04,36.48 32.18,36.63 32.18,36.77 32.07,36.88 32.07,37.03 32.21,37.17 32.36,37.17 32.47,37.06 32.61,37.06 v2(33.1,37.54)
  BOTTOM w0.102: 58.69,49.63 57.99,49.63
  BOTTOM w0.127: v2(33.1,37.54) 33.48,37.54 33.6,37.42 33.6,35.84 33.73,35.71 33.99,35.71 34.11,35.84 34.11,36.02 34.24,36.15 34.49,36.15 34.87,35.77 35.34,35.77 35.6,36.02 36,36.02 36.26,35.77 36.66,35.77 36.92,36.02 37.32,36.02 37.58,35.77 37.98,35.77 38.24,36.02 38.64,36.02 38.9,35.77 39.32,35.77 49.53,45.98 49.94,45.98 50.11,45.8 50.5,45.8 50.75,46.05 50.75,46.33 50.9,46.48 51.18,46.48 52.1,47.4 52.1,48.26 52.37,48.54 52.37,48.83 52.59,49.05 54.2,49.05 54.41,48.85 54.41,48.54 54.52,48.43 55.11,48.43 55.4,48.72 55.7,48.72 55.83,48.85 55.83,49.02 55.96,49.15 56.21,49.15 56.34,49.02 56.34,48.85 56.46,48.72 57.73,48.72 57.86,48.85 57.86,49.5 57.99,49.63 ; 58.69,49.63 59.56,50.5 59.56,51.54 60.16,52.14 60.41,52.14 v1(60.72,52.45)
H_DDR1_D9: length 42.8
  TOP w0.127: v1(35.08,32.1) U65.B8 ; U52.AF27 57.58,48.5 57.58,45.18 57.18,44.78 56.76,44.78 56.71,44.83 55.52,44.83 55.17,45.19 53.14,45.19 52.4,45.93 52.12,45.93 51.97,45.77 v2(51.97,45.29)
  L3-SIGNAL w0.114: v1(35.08,32.1) 35.84,32.85 35.84,33.52 35.74,33.62 35.12,33.62 35,33.74 35,33.91 35.12,34.03 35.74,34.03 35.84,34.13 35.84,36.65 36.07,36.89 36.22,36.89 36.42,36.69 36.56,36.69 36.7,36.83 36.7,36.98 36.51,37.18 36.51,37.32 36.65,37.47 36.79,37.47 36.99,37.27 37.14,37.27 37.28,37.41 37.28,37.55 37.08,37.75 37.08,37.9 37.22,38.04 37.37,38.04 37.57,37.84 37.71,37.84 37.86,37.98 37.86,38.13 37.66,38.33 37.66,38.47 37.8,38.62 37.94,38.62 38.14,38.42 38.29,38.42 38.43,38.56 38.43,38.7 38.23,38.9 38.23,39.05 38.37,39.19 38.52,39.19 38.72,38.99 38.86,38.99 39.01,39.13 39.01,39.28 38.81,39.48 38.81,39.62 39.01,39.83 39.45,39.83 40.21,39.07 44.2,39.07 46.24,41.11 46.24,41.93 47.13,42.81 47.64,42.81 47.83,43 47.83,43.51 48.97,44.66 49.81,44.66 49.94,44.78 49.94,45.37 50.06,45.49 50.39,45.49 50.6,45.29 v2(51.97,45.29)
H_DDR1_D10: length 43.7
  TOP w0.127: U52.AG27 57.13,48.58 56.74,48.19 56.74,47.77 55.79,46.81 52.98,46.81 52.6,46.43 v2(50.19,46.43) ; v1(34.28,32.9) U65.A7
  L3-SIGNAL w0.114: v2(50.19,46.43) 49.71,46.43 49.59,46.32 49.59,45.79 49.48,45.67 48.95,45.67 48.53,45.26 48.53,45.12 48.62,45.03 48.62,44.89 48.47,44.74 48.33,44.74 48.25,44.83 48.1,44.83 47.96,44.68 47.96,44.54 48.04,44.46 48.04,44.31 47.9,44.17 47.76,44.17 47.67,44.25 47.53,44.25 47.38,44.11 47.38,43.97 47.47,43.88 47.47,43.74 47.32,43.59 47.18,43.59 47.1,43.68 46.95,43.68 46.81,43.53 46.81,43.39 46.89,43.31 46.89,43.16 46.75,43.02 46.61,43.02 46.52,43.1 46.38,43.1 46.23,42.96 46.23,42.82 46.32,42.73 46.32,42.59 45.8,42.06 45.8,41.23 44.15,39.58 40.34,39.58 39.57,40.34 38.89,40.34 38.19,39.64 38.04,39.64 37.89,39.79 37.75,39.79 37.61,39.64 37.61,39.5 37.83,39.27 37.83,39.11 37.71,38.99 37.55,38.99 37.32,39.21 37.18,39.21 37.03,39.07 37.03,38.92 37.26,38.7 37.26,38.53 37.14,38.41 36.97,38.41 36.74,38.64 36.6,38.64 36.46,38.49 36.46,38.35 36.68,38.12 36.68,37.95 36.56,37.84 36.39,37.84 36.17,38.06 36.03,38.06 35.88,37.92 35.88,37.77 36.03,37.62 36.03,37.48 35.89,37.34 35.74,37.34 35.59,37.49 35.45,37.49 35.31,37.34 35.31,37.2 35.46,37.05 35.46,36.91 35.31,36.76 35.17,36.76 35.02,36.91 34.88,36.91 34.73,36.77 34.73,36.62 34.88,36.47 34.88,36.33 34.62,36.07 34.62,35.84 34.72,35.74 35.26,35.74 35.38,35.62 35.38,35.45 35.26,35.33 34.54,35.33 34.42,35.21 34.42,35.05 34.54,34.93 35.26,34.93 35.38,34.81 35.38,34.64 35.26,34.52 34.72,34.52 34.62,34.42 34.62,34.25 34.52,34.15 34.09,34.15 33.99,34.05 33.99,33.85 34.09,33.75 34.52,33.75 34.62,33.65 34.62,33.23 v1(34.28,32.9)
H_DDR1_D11: length 41.9
  TOP w0.127: U52.AF28 57.93,45.17 57.29,44.53 56.55,44.53 56.51,44.57 54.98,44.57 54.76,44.78 v2(51.21,44.78) ; v1(35.08,31.3) U65.C8
  L3-SIGNAL w0.114: v1(35.08,31.3) 36.09,31.3 36.35,31.55 36.35,35.84 36.64,36.14 36.79,36.14 37.03,35.9 37.17,35.9 37.31,36.05 37.31,36.19 37.08,36.43 37.08,36.57 37.22,36.71 37.36,36.71 37.6,36.48 37.74,36.48 37.89,36.62 37.89,36.76 37.65,37 37.65,37.14 37.79,37.29 37.94,37.29 38.18,37.05 38.32,37.05 38.46,37.2 38.46,37.34 38.23,37.58 38.23,37.72 38.37,37.86 38.51,37.86 38.75,37.63 38.89,37.63 39.04,37.77 39.04,37.91 38.8,38.15 38.8,38.29 38.94,38.44 39.09,38.44 39.33,38.2 39.47,38.2 39.61,38.35 39.61,38.49 39.38,38.73 39.38,38.87 39.52,39.01 39.66,39.01 40.12,38.56 44.27,38.56 46.43,40.72 46.56,40.72 46.93,41.09 46.93,41.24 46.63,41.54 46.63,41.68 46.77,41.82 46.92,41.82 47.16,41.59 47.32,41.59 47.44,41.71 47.44,41.87 47.21,42.11 47.21,42.26 47.35,42.4 47.49,42.4 47.79,42.1 47.94,42.1 48.21,42.37 49.96,42.37 50.88,43.28 50.88,44.1 51.21,44.43 v2(51.21,44.78)
H_DDR1_D12: length 44.9
  TOP w0.102: v1(58.34,49.25) U52.AE26
  TOP w0.127: v2(34.06,37.04) 34.06,36.58 31.65,34.17 31.65,31.24 31.3,30.89 U65.C3
  L3-SIGNAL w0.114: v1(58.34,49.25) 57.4,49.25 57.23,49.08 57.23,48.94 57.34,48.83 57.34,48.68 57.2,48.54 57.06,48.54 56.94,48.65 56.8,48.65 56.52,48.36 56.18,48.36 56.08,48.47 55.22,48.47 55.12,48.36 53.37,48.36 53.22,48.52 52.85,48.52 52.58,48.24 52.58,47.53 52.27,47.22 52.27,45.93 52.15,45.8 50.88,45.8 50.75,45.93 50.75,46.76 50.62,46.89 49.33,46.89 49.2,46.76 49.2,46.26 49.03,46.09 48.65,46.09 45.42,42.85 45.42,41.48 43.99,40.06 40.49,40.06 39.7,40.85 38.81,40.85 38.56,40.59 38.3,40.59 38.05,40.85 37.87,40.85 37.47,40.44 37.47,40.3 37.54,40.22 37.54,40.08 37.39,39.94 37.25,39.94 37.18,40.01 37.04,40.01 36.89,39.87 36.89,39.72 36.96,39.65 36.96,39.51 36.82,39.36 36.68,39.36 36.6,39.43 36.46,39.43 36.32,39.29 36.32,39.15 36.39,39.07 36.39,38.93 36.24,38.79 36.1,38.79 36.03,38.86 35.89,38.86 35.74,38.72 35.74,38.57 35.81,38.5 35.81,38.36 35.67,38.21 35.53,38.21 35.45,38.28 35.31,38.28 35.17,38.14 35.17,38 35.24,37.92 35.24,37.78 35.09,37.64 34.95,37.64 34.88,37.71 34.73,37.71 v2(34.06,37.04)
H_DDR1_D13: length 47.3
  TOP w0.102: U52.AC25 v1(60.83,49.82)
  TOP w0.127: v1(33.48,30.5) U65.D7
  BOTTOM w0.102: 57.47,47.2 57.06,46.79
  BOTTOM w0.127: 57.06,46.79 57.02,46.75 57.02,46 56.87,45.85 55.77,45.85 54.69,44.77 52.77,44.77 52.54,44.54 52.39,44.54 52.15,44.78 51.89,44.78 51.05,43.94 51.05,43.36 50.19,42.5 48.84,42.5 48.31,41.96 47.52,41.96 38.91,33.35 38.77,33.35 38.67,33.25 38.67,32.82 38.57,32.72 38.36,32.72 38.26,32.82 38.26,33.25 38.16,33.35 37.96,33.35 37.85,33.25 37.85,32.35 37.73,32.24 37.57,32.24 37.45,32.35 37.45,33.25 37.35,33.35 37.14,33.35 37.04,33.25 37.04,32.46 36.92,32.34 36.75,32.34 36.63,32.46 36.63,33.25 36.53,33.35 36.33,33.35 36.23,33.25 36.23,32.74 36.11,32.62 35.94,32.62 35.82,32.74 35.82,33.2 35.69,33.33 33.1,33.33 32.89,33.12 32.89,30.66 33.06,30.5 v1(33.48,30.5) ; v1(60.83,49.82) 60.48,49.66 60.29,49.47 60.29,48.68 59.16,47.55 58.68,47.55 58.58,47.45 58.58,47.3 58.48,47.2 58.28,47.2 58.18,47.3 58.18,47.45 58.08,47.55 57.87,47.55 57.77,47.45 57.77,47.3 57.67,47.2 57.47,47.2
H_DDR1_D14: length 49.5
  TOP w0.102: v1(60.73,51.7) U52.AC24
  TOP w0.127: U65.A3 30.68,33.01 30.58,33.11 30.4,33.11 30.3,33.21 30.3,33.42 30.4,33.52 30.58,33.52 30.68,33.62 30.68,34.37 v2(33.1,36.78)
  BOTTOM w0.127: v1(60.73,51.7) 60.28,51.7 59.89,51.31 59.89,50.24 59.46,49.81 59.46,49.56 59.59,49.43 59.59,49.1 58.95,48.47 58.24,48.47 58.09,48.31 57.56,48.31 56.9,47.65 55.47,47.65 55.05,48.08 54.35,48.08 53.68,48.75 53.01,48.75 52.4,48.14 52.4,47.25 50.44,45.29 50.11,45.29 49.99,45.16 49.99,44.78 49.86,44.66 48.64,44.66 46.28,42.29 46.28,42.01 39.01,34.75 38.75,34.75 38.65,34.85 38.65,35.16 38.55,35.26 38.35,35.26 38.25,35.16 38.25,34.85 38.14,34.75 37.94,34.75 37.84,34.85 37.84,35.16 37.74,35.26 37.53,35.26 37.43,35.16 37.43,34.85 37.33,34.75 37.13,34.75 37.03,34.85 37.03,35.16 36.92,35.26 36.72,35.26 36.62,35.16 36.62,34.85 36.52,34.75 36.31,34.75 36.21,34.85 36.21,35.16 36.11,35.26 35.91,35.26 35.81,35.16 35.81,34.85 35.7,34.75 35.5,34.75 35.4,34.85 35.4,35.16 35.3,35.26 35.1,35.26 34.99,35.16 34.99,34.85 34.89,34.75 33.99,34.75 33.1,35.64 v2(33.1,36.78)
H_DDR1_D15: length 45.2
  TOP w0.102: v1(58.73,50.43) U52.AD25
  TOP w0.127: U65.C2 30.31,31.32 31.06,31.32 31.22,31.47 31.22,34.19 33.55,36.53 33.55,37.42 v2(34.06,37.92)
  L3-SIGNAL w0.102: v1(58.73,50.43) 57.97,50.43
  L3-SIGNAL w0.114: v2(34.06,37.92) 37.49,41.35 43.21,41.35 49.07,47.22 51.05,47.22 51.18,47.09 51.18,46.31 51.31,46.18 51.69,46.18 51.82,46.31 51.82,47.37 52.22,47.78 52.22,48.47 52.88,49.13 54.36,49.13 54.84,49.61 55.49,49.61 55.62,49.48 55.62,48.91 55.74,48.8 55.9,48.8 56.02,48.91 56.02,49.51 56.12,49.61 56.33,49.61 56.43,49.51 56.43,49.17 56.55,49.05 56.72,49.05 56.84,49.17 56.84,49.78 56.97,49.91 57.15,49.91 57.45,49.61 57.71,49.61 57.84,49.74 57.84,50.3 57.97,50.43
H_DDR1_D16: length 38.1
  TOP w0.102: v1(64.77,54.87) U52.V20
  TOP w0.127: U66.F8 v1(47.78,28.09)
  L3-SIGNAL w0.102: 64.37,54.47 62.98,54.47 62.74,54.23
  L3-SIGNAL w0.114: 64.37,54.47 v1(64.77,54.87) ; 62.74,54.23 62.74,53.09 62.26,52.61 62.26,50.98 61.65,50.37 60.78,50.37 60.33,49.91 60.33,48.57 58.32,46.56 58.32,45.67 56.97,44.33 56.97,43.94 56.46,43.44 56.08,43.44 48.18,35.54 48.18,31.73 47.4,30.94 47.4,29.36 47.26,29.23 46.86,29.23 46.74,29.11 46.74,28.94 46.86,28.82 47.66,28.82 47.78,28.69 v1(47.78,28.09)
H_DDR1_D17: length 38.1
  TOP w0.102: v1(63.17,54.05) U52.W20
  TOP w0.127: U66.H8 v1(47.78,27.29)
  L3-SIGNAL w0.114: v1(63.17,54.05) 63.17,53.78 63.53,53.42 63.53,53.09 63.3,52.86 62.97,52.86 62.66,52.55 62.66,51.74 62.51,51.59 62.51,50.73 61.78,50 61.78,49.01 61.01,48.24 61.01,47.86 59.21,46.05 59.21,44.53 57.01,42.33 56.86,42.33 56.71,42.48 56.57,42.48 56.43,42.33 56.43,42.19 56.57,42.04 56.57,41.9 56.43,41.75 56.29,41.75 56.14,41.9 55.99,41.9 55.85,41.76 55.85,41.61 56,41.46 56,41.32 55.86,41.18 55.71,41.18 55.56,41.33 55.42,41.33 55.28,41.18 55.28,41.04 55.42,40.89 55.42,40.75 55.28,40.6 55.14,40.6 54.99,40.75 54.84,40.75 54.7,40.61 54.7,40.46 54.85,40.31 54.85,40.17 54.7,40.03 54.56,40.03 54.41,40.18 54.27,40.18 54.13,40.03 54.13,39.89 54.27,39.74 54.27,39.6 49.94,35.26 49.94,28.65 48.96,27.68 48.17,27.68 v1(47.78,27.29)
H_DDR1_D18: length 32.3
  TOP w0.127: U66.F7 46.05,29.03 46.05,29.59 45.92,29.72 45.49,29.72 45.36,29.85 45.36,35.59 46.84,37.06 50.47,37.06 51.64,38.23 55.98,38.23 56.34,38.59 58.14,40.39 59.51,40.39 59.99,40.87 59.99,43.28 60.5,43.79 60.5,46.64 61.13,47.26 61.13,48.05
H_DDR1_D19: length 42.7
  TOP w0.127: v2(47.7,38.43) 50.6,38.43 51.1,38.94 55.06,38.94 57.14,41.02 58.83,41.02 59.36,41.56 59.36,43.67 59.94,44.25 59.94,46.89 60.33,47.28 U52.AC28 ; v1(42.98,28.9) U66.F2
  L3-SIGNAL w0.114: v2(47.7,38.43) 47.02,38.43 46.8,38.21 46.8,38.07 47.47,37.4 47.47,37.23 47.35,37.11 47.18,37.11 46.51,37.78 46.36,37.78 46.22,37.64 46.22,37.49 46.73,36.99 46.73,36.82 46.61,36.7 46.44,36.7 45.93,37.21 45.79,37.21 45.11,36.53 45.11,36.03 45.21,35.93 45.57,35.93 45.67,35.83 45.67,35.62 45.57,35.52 45.21,35.52 45.11,35.42 45.11,35.22 45.21,35.12 45.57,35.12 45.67,35.01 45.67,34.81 45.57,34.71 45.21,34.71 45.11,34.61 45.11,34.4 45.21,34.3 45.57,34.3 45.67,34.2 45.67,34 45.57,33.9 45.21,33.9 45.11,33.79 45.11,33.59 45.21,33.49 45.57,33.49 45.67,33.39 45.67,33.18 45.57,33.08 45.21,33.08 45.11,32.98 45.11,32.78 45.21,32.68 45.57,32.68 45.67,32.58 45.67,32.37 45.57,32.27 45.21,32.27 45.11,32.17 45.11,31.97 45.21,31.86 45.57,31.86 45.67,31.76 45.67,31.56 45.57,31.46 45.21,31.46 45.11,31.36 45.11,31.15 45.21,31.05 45.57,31.05 45.67,30.95 45.67,30.75 45.57,30.64 45.21,30.64 45.11,30.54 45.11,30.05 43.95,28.9 v1(42.98,28.9)
H_DDR1_D20: length 42.4
  TOP w0.127: U52.AC27 59.89,48.41 59.89,47.27 59.59,46.97 59.59,44.4 57.85,42.66 57.84,42.66 57.8,42.62 57.2,42.62 55.68,41.1 54.69,41.1 54.05,40.46 54.05,39.83 53.54,39.32 52.02,39.32 51.74,39.6 51.13,39.6 50.47,38.94 46.51,38.94 v2(45.36,37.8) ; v1(43.78,29.7) U66.E3
  L3-SIGNAL w0.114: v1(43.78,29.7) 44.48,30.39 44.48,31.68 44.37,31.78 43.73,31.78 43.61,31.9 43.61,32.07 43.73,32.18 44.37,32.18 44.48,32.29 44.48,33.5 44.37,33.6 43.38,33.6 43.26,33.72 43.26,33.89 43.38,34.01 44.37,34.01 44.48,34.11 44.48,34.32 44.37,34.42 43.38,34.42 43.26,34.54 43.26,34.7 43.38,34.82 44.37,34.82 44.48,34.93 44.48,35.13 44.37,35.23 43.23,35.23 43.13,35.33 43.13,35.53 43.23,35.64 44.37,35.64 44.48,35.74 44.48,35.94 44.37,36.04 43.23,36.04 43.13,36.14 43.13,36.35 43.23,36.45 44.37,36.45 44.48,36.55 44.48,36.91 v2(45.36,37.8)
H_DDR1_D21: length 38.7
  TOP w0.102: v1(63.15,54.89) U52.Y19
  TOP w0.127: v1(42.98,28.09) U66.G2
  L3-SIGNAL w0.102: v1(63.15,54.89) 63.05,54.79 62.81,54.79 62.49,54.48 62.09,54.48
  L3-SIGNAL w0.114: 62.09,54.48 61.93,54.31 61.93,53.79 60.99,52.86 60.58,52.86 60.33,52.61 60.33,51.56 59.87,51.11 59.87,50.35 59.64,50.12 59.64,49.02 57.3,46.69 56.92,46.69 56.62,46.39 56.62,46.08 56.39,45.85 55.91,45.85 55.65,45.6 55.65,45.11 52.78,42.24 52.15,42.24 51.44,41.54 51.44,41.3 51.18,41.04 50.95,41.04 50.72,40.82 50.72,40.52 50.29,40.08 49.99,40.08 48.72,38.81 48.72,37.54 46.05,34.88 46.05,30.1 44.04,28.09 v1(42.98,28.09)
H_DDR1_D22: length 41.8
  TOP w0.127: 61.13,48.85 60.69,48.41 60.69,47.23 60.22,46.76 60.22,44.02 59.69,43.49 59.69,41.15 59.23,40.69 57.71,40.69 55.6,38.59 51.36,38.59 50.7,37.92 46.89,37.92 43.67,34.7 42.74,34.7 42.62,34.58 42.62,34.42 42.74,34.3 44.88,34.3 44.98,34.19 44.98,29.37 45.09,29.27 45.55,29.27 45.67,29.15 45.67,28.98 45.55,28.86 45.15,28.86 45.03,28.74 45.03,28.58 45.15,28.46 45.55,28.46 45.67,28.34 45.67,28.17 45.55,28.05 45.15,28.05 45.03,27.93 45.03,27.76 45.15,27.64 45.54,27.64 45.67,27.51 45.67,26.75 45.8,26.62 46.31,26.62 U66.H7
H_DDR1_D23: length 38.5
  TOP w0.102: v1(44.58,27.3) 43.79,27.3 U66.H3 ; U52.Y20 v1(62.31,54.04)
  L3-SIGNAL w0.114: v1(44.58,27.3) 44.58,27.74 45.12,28.28 45.26,28.28 45.4,28.14 45.54,28.14 45.68,28.29 45.68,28.43 45.55,28.57 45.55,28.71 46.56,29.72 46.56,32.46 47.07,32.97 47.07,35.13 49.35,37.42 49.35,38.69 52.27,41.61 53.85,41.61 55.45,43.21 55.45,43.92 56.46,44.94 56.95,44.94 57.87,45.86 57.87,46.65 59.94,48.72 59.94,49.94 60.27,50.27 60.27,50.96 60.58,51.26 61.75,51.26 61.98,51.49 61.98,53.08 62.31,53.42 v1(62.31,54.04)
H_DDR1_D24: length 42.2
  TOP w0.102: v1(61.53,52.41) U52.AA23
  TOP w0.127: v1(43.78,31.3) U66.C3
  BOTTOM w0.127: v1(43.78,31.3) 44.26,31.77 44.4,31.77 45.07,31.1 45.24,31.1 45.36,31.22 45.36,31.38 44.69,32.06 44.69,32.2 44.83,32.34 44.98,32.34 45.63,31.68 45.78,31.68 45.92,31.83 45.92,31.97 45.26,32.63 45.26,32.77 47.35,34.86 47.35,35 47.04,35.31 47.04,35.48 47.16,35.6 47.32,35.6 47.63,35.29 47.78,35.29 47.92,35.43 47.92,35.58 47.62,35.88 47.62,36.04 47.74,36.16 47.91,36.16 48.21,35.86 48.35,35.86 48.63,36.15 49.08,36.15 49.2,36.02 49.61,36.02 49.74,36.15 51,36.15 51.13,36.27 51.13,36.58 51.26,36.71 51.46,36.71 51.59,36.58 51.59,36.25 51.69,36.15 51.89,36.15 51.99,36.25 51.99,36.68 52.1,36.78 52.4,36.78 53.36,37.74 53.36,38.14 53.11,38.39 53.11,38.56 53.23,38.67 53.39,38.67 53.95,38.12 54.12,38.12 54.24,38.24 54.24,38.41 53.82,38.82 53.82,38.97 53.97,39.11 54.11,39.11 54.4,38.82 54.57,38.82 54.69,38.94 54.69,39.11 54.4,39.4 54.4,39.54 54.84,39.98 54.84,41.05 62.2,48.41 62.2,51.73 v1(61.53,52.41)
H_DDR1_D25: length 42.8
  TOP w0.102: U52.Y22 v1(63.13,53.25)
  TOP w0.127: v1(46.58,33.23) U66.A7
  BOTTOM w0.127: v1(63.13,53.25) 62.47,52.59 62.47,48.25 55.12,40.9 55.12,39.74 55.58,39.28 55.58,38.94 55.16,38.53 55.16,38.38 55.4,38.15 55.4,38 55.25,37.86 55.11,37.86 54.87,38.1 54.73,38.1 54.59,37.95 54.59,37.81 54.82,37.57 54.82,37.43 54.68,37.28 54.54,37.28 54.3,37.52 54.15,37.52 54.01,37.38 54.01,37.23 54.25,37 54.25,36.85 54.1,36.71 53.96,36.71 53.72,36.95 53.58,36.95 53.44,36.8 53.44,36.66 53.67,36.42 53.67,36.28 53.53,36.13 53.39,36.13 53.15,36.37 53,36.37 52.86,36.23 52.86,36.08 53.1,35.85 53.1,35.7 52.95,35.56 52.81,35.56 52.57,35.8 52.43,35.8 52.15,35.51 51.42,35.51 51.32,35.41 51.32,34.74 51.2,34.62 51.03,34.62 50.91,34.74 50.91,35.27 50.79,35.38 50.63,35.38 50.51,35.27 50.51,34.74 50.39,34.62 50.22,34.62 50.1,34.74 50.1,35.26 49.97,35.38 49.79,35.38 49.67,35.26 49.67,34.74 49.55,34.62 49.38,34.62 49.26,34.74 49.26,35.11 49.13,35.23 48.43,35.23 48.31,35.11 48.31,34.81 48.58,34.53 48.58,34.36 48.44,34.22 48.26,34.22 47.96,34.52 47.72,34.52 47.14,33.94 47.14,31.75 47.02,31.63 46.71,31.63 46.58,31.75 v1(46.58,33.23)
H_DDR1_D26: length 40.1
  TOP w0.102: U52.Y23 v1(63.12,52.45)
  TOP w0.127: v1(47.78,32.1) U66.B8
  BOTTOM w0.102: 62.73,48.06 61.46,46.79
  BOTTOM w0.127: 61.46,46.79 55.47,40.8 55.47,40.03 56.08,39.42 56.08,38.23 55.05,37.19 55.05,36.14 53.83,34.93 52.58,34.93 51.69,34.04 51.69,32.58 51.57,32.46 51.4,32.46 51.28,32.58 51.28,34.01 51.18,34.11 50.98,34.11 50.88,34.01 50.88,32.58 50.76,32.46 50.59,32.46 50.47,32.58 50.47,34.01 50.37,34.11 50.16,34.11 50.06,34.01 50.06,32.58 49.94,32.46 49.78,32.46 49.66,32.58 49.66,34.01 49.56,34.11 49.35,34.11 49.24,34 49.24,32.72 49.01,32.49 48.18,32.49 v1(47.78,32.1) ; v1(63.12,52.45) 62.73,52.05 62.73,48.06
H_DDR1_D27: length 42.2
  TOP w0.102: v1(61.48,50.85) U52.AA24
  TOP w0.127: v1(43.78,32.9) U66.A3
  BOTTOM w0.102: 61.82,50.18 61.96,50.04 61.96,48.76
  BOTTOM w0.127: v1(61.48,50.85) 61.48,50.52 61.82,50.18 ; 61.96,48.76 61.96,48.61 54.54,41.18 54.54,40.73 54.42,40.61 54.25,40.61 53.91,40.95 53.77,40.95 53.63,40.8 53.63,40.66 54.04,40.24 54.04,40.07 53.92,39.96 53.75,39.96 53.34,40.37 53.2,40.37 53.05,40.23 53.05,40.08 53.47,39.67 53.47,39.5 53.35,39.38 53.18,39.38 52.91,39.65 52.61,39.65 52.35,39.4 52.35,38.5 52.57,38.28 52.57,38.12 52.45,38 52.28,38 52.07,38.21 51.92,38.21 51.78,38.06 51.78,37.92 52.08,37.62 52.08,37.48 51.93,37.33 51.79,37.33 51.55,37.57 50.99,37.57 50.73,37.32 50.73,36.77 50.61,36.65 50.44,36.65 50.33,36.77 50.33,37.32 50.22,37.42 50.02,37.42 49.92,37.32 49.92,36.77 49.8,36.65 49.63,36.65 49.51,36.77 49.51,37.32 49.41,37.42 49.18,37.42 49.08,37.32 49.08,36.77 48.96,36.65 48.79,36.65 48.67,36.77 48.67,37.32 48.57,37.42 48.37,37.42 48.27,37.32 48.27,36.77 48.15,36.65 47.98,36.65 47.86,36.77 47.86,37.32 47.76,37.42 47.56,37.42 47.46,37.32 47.46,37.05 47.34,36.93 47.17,36.93 47.05,37.05 47.05,37.25 46.93,37.37 46.74,37.37 46.61,37.24 46.61,37.04 46.48,36.91 45.8,36.91 45.18,36.3 45.18,36.15 45.3,36.04 45.3,35.9 45.15,35.76 45.01,35.76 44.9,35.87 44.75,35.87 44.61,35.72 44.61,35.58 44.73,35.45 44.73,35.29 44.61,35.17 44.45,35.17 44.32,35.29 44.18,35.29 43.78,34.9 43.78,34.16 43.68,34.06 43.48,34.06 43.38,33.96 43.38,33.75 43.48,33.65 43.68,33.65 43.78,33.55 v1(43.78,32.9)
H_DDR1_D28: length 39.5
  TOP w0.102: v1(63.13,51.7) U52.Y24
  TOP w0.127: v2(50.95,31.83) 50.42,31.3 47.78,31.3 U66.C8
  L3-SIGNAL w0.102: 62.76,51.34 62.76,50.52
  L3-SIGNAL w0.114: v2(50.95,31.83) 50.95,34.2 50.84,34.31 50.61,34.31 50.5,34.43 50.5,34.66 50.61,34.77 50.84,34.77 50.95,34.89 50.95,35.46 51.2,35.71 51.51,35.71 51.84,35.37 52.01,35.37 52.13,35.49 52.13,35.66 51.62,36.17 51.62,36.31 51.77,36.45 51.91,36.45 52.38,35.99 52.52,35.99 52.66,36.13 52.66,36.28 52.2,36.74 52.2,36.88 52.34,37.03 52.49,37.03 52.95,36.56 53.1,36.56 53.24,36.71 53.24,36.85 52.77,37.32 52.77,37.46 52.92,37.6 53.06,37.6 53.53,37.14 53.67,37.14 53.81,37.28 53.81,37.43 53.35,37.89 53.35,38.03 53.49,38.18 53.64,38.18 54.1,37.71 54.25,37.71 54.39,37.86 54.39,38 53.92,38.47 53.92,38.61 54.07,38.75 54.21,38.75 54.68,38.29 54.82,38.29 54.96,38.43 54.96,38.58 54.56,38.98 54.56,39.4 55.14,39.98 56.16,39.98 56.52,40.34 56.52,41.33 57.71,42.52 57.84,42.52 59.72,44.4 59.72,45.93 61.42,47.63 61.42,48.14 62.08,48.8 62.08,49.84 62.76,50.52 ; v1(63.13,51.7) 62.76,51.34
